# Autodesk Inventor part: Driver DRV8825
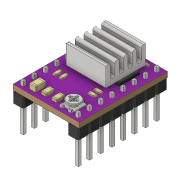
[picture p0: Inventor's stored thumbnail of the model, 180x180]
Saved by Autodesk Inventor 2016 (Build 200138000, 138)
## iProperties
Created: 2019-05
Part Number: Driver DRV8825
Material: Generic
Document SubType Name: Modeling
Designer: Wesley Perez
Density: 1 g/cm^3
Appearance: Default
Sending System: Autodesk Inventor 2016
Preprocessor: ST-DEVELOPER v16.1
Title: D:\ADEBOTT ENGENHARIA\Dep. PROJETOS\BIBLIOTECAS\Impressora 3D\Driver DRV8825.stp
Author: Adebott Projetos
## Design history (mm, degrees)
feature "Sup2"
feature "Sup3"
feature "Sup3:1"
feature "Sup3:2"
feature "Sup3:3"
feature "Sup3:4"
feature "Sup3:5"
feature "Sup3:6"
feature "Sup3:7"
feature "Sup3:8"
feature "Sup3:9"
feature "Sup3:10"
feature "Sup3:11"
feature "Sup3:12"
feature "Sup3:13"
feature "Sup3:14"
feature "Sup3:15"
feature "Sup4"
feature "Sup5"
feature "Sup5:1"
feature "Sup5:2"
feature "Sup5:3"
feature "Sup5:4"
feature "Sup5:5"
feature "Sup5:6"
feature "Sup5:7"
feature "Sup5:8"
feature "Sup5:9"
feature "Sup5:10"
feature "Sup5:11"
feature "Sup5:12"
feature "Sup5:13"
feature "Sup5:14"
feature "Sup5:15"
feature "Sup6"
feature "Sup6:1"
feature "Sup6:2"
feature "Sup6:3"
feature "Sup6:4"
feature "Sup7"
feature "Sup7:1"
feature "Sup7:2"
feature "Sup7:3"
feature "Sup7:4"
feature "Sup7:5"
feature "Sup7:6"
feature "Sup7:7"
feature "Sup7:8"
feature "Sup7:9"
feature "Sup8"
node "Sólido1"
node "Sólido2"
node "Sólido3"
node "Sólido4"
node "Sólido5"
node "Sólido6"
node "Sólido7"
node "Sólido8"
node "Sólido9"
node "Sólido10"
node "Sólido11"
node "Sólido12"
node "Sólido13"
node "Sólido14"
node "Sólido15"
node "Sólido16"
node "Sólido17"
node "Sólido18"
node "Sólido19"
node "Sólido20"
node "Sólido21"
node "Sólido22"
node "Sólido23"
node "Sólido24"
node "Sólido25"
node "Sólido26"
node "Sólido27"
node "Sólido28"
node "Sólido29"
node "Sólido30"
node "Sólido31"
node "Sólido32"
node "Sólido33"
node "Sólido34"
node "Sólido35"
node "Sólido36"
node "Sólido37"
node "Sólido38"
node "Sólido39"
node "Sólido40"
node "Sólido41"
node "Sólido42"
node "Sólido43"
node "Sólido44"
node "Sólido45"
node "Sólido46"
node "Sólido47"
node "Sólido48"
node "Sólido49"
node "Sólido50"
